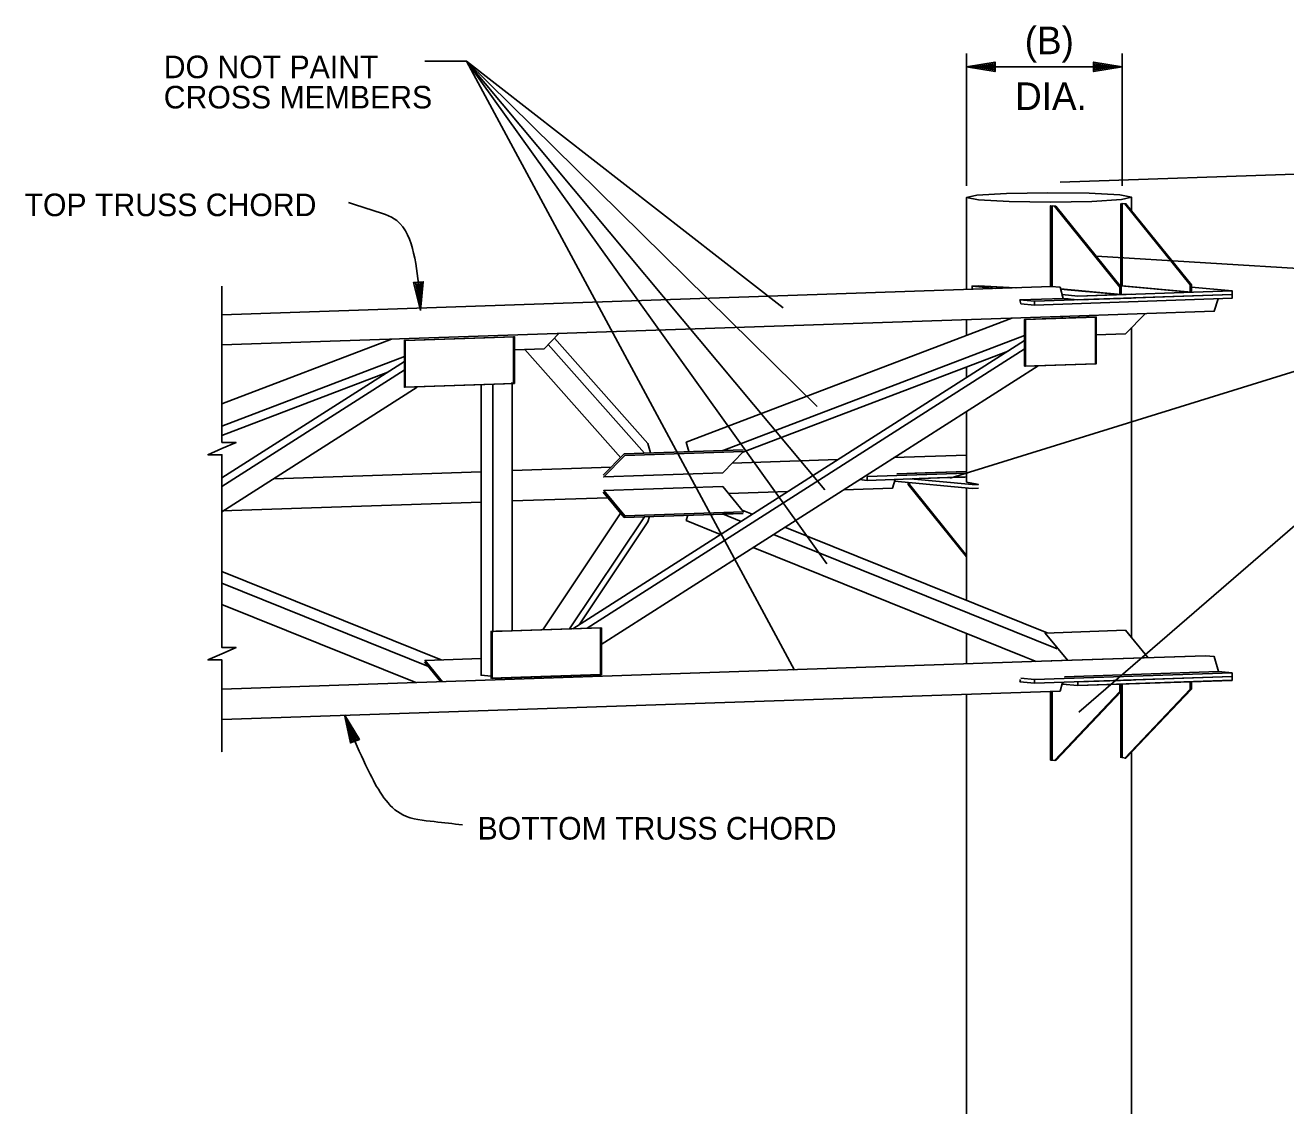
# Model space of a CAD drawing. Extents: x 10268852 to 10269008, y 2142584 to 2142686.
# Drawn here: x 10268877.93 to 10268915.89, y 2142653.26 to 2142685.79 of the extents above; entities that cross this region are included whole.
import ezdxf

# ---------------------------------------------------------------- set-up
doc = ezdxf.new("R2010")
doc.units = 0
doc.layers.add('SignDetail', color=7, linetype='Continuous')
doc.layers.add('TextLabel', color=7, linetype='Continuous')

msp = doc.modelspace()

# ---------------------------------------------------------------- linework, layer by layer
at = {"layer": 'SignDetail'}
msp.add_line((10268914.272, 2142666.07), (10268914.272, 2142666.183), dxfattribs=at)
for points in [[(10268906.277, 2142680.609), (10268906.588, 2142680.679), (10268907.481, 2142680.731), (10268908.717, 2142680.751), (10268909.965, 2142680.734), (10268910.89, 2142680.683), (10268911.246, 2142680.614)], [(10268910.89, 2142680.683), (10268909.965, 2142680.734), (10268908.717, 2142680.751), (10268907.481, 2142680.731), (10268906.588, 2142680.679), (10268906.277, 2142680.609), (10268906.632, 2142680.539), (10268907.558, 2142680.488), (10268908.806, 2142680.471), (10268910.042, 2142680.491), (10268910.935, 2142680.543), (10268911.246, 2142680.614), (10268910.89, 2142680.683)], [(10268906.277, 2142680.609), (10268906.588, 2142680.68)], [(10268906.588, 2142680.68), (10268907.481, 2142680.732)], [(10268907.481, 2142680.732), (10268908.717, 2142680.752)], [(10268908.717, 2142680.752), (10268909.965, 2142680.734)], [(10268909.965, 2142680.734), (10268910.891, 2142680.684), (10268911.246, 2142680.614)], [(10268906.277, 2142677.842), (10268906.277, 2142680.609), (10268906.632, 2142680.539), (10268907.558, 2142680.488), (10268908.806, 2142680.471), (10268910.042, 2142680.491), (10268910.935, 2142680.543), (10268911.246, 2142680.614), (10268911.246, 2142680.208)], [(10268908.806, 2142677.928), (10268908.806, 2142680.359), (10268908.806, 2142677.928)], [(10268908.806, 2142677.928), (10268908.806, 2142680.359), (10268908.922, 2142680.349), (10268910.891, 2142677.908)], [(10268908.806, 2142680.359), (10268908.806, 2142677.928)], [(10268908.806, 2142680.359), (10268908.922, 2142680.349)], [(10268908.842, 2142680.361), (10268908.842, 2142677.927)], [(10268908.842, 2142680.361), (10268908.842, 2142677.927)], [(10268908.856, 2142680.359), (10268908.958, 2142680.35), (10268910.927, 2142677.909), (10268910.927, 2142677.684), (10268909.102, 2142677.855)], [(10268908.856, 2142680.359), (10268908.958, 2142680.35)], [(10268908.856, 2142680.344), (10268908.856, 2142677.925), (10268908.856, 2142680.344)], [(10268910.891, 2142677.683), (10268910.891, 2142677.908), (10268908.922, 2142680.349)], [(10268909.102, 2142677.855), (10268910.927, 2142677.684), (10268910.927, 2142677.909), (10268908.958, 2142680.35)], [(10268913.006, 2142677.754), (10268910.921, 2142677.95), (10268910.921, 2142680.431)], [(10268911.038, 2142680.42), (10268913.006, 2142677.98), (10268913.006, 2142677.754), (10268910.921, 2142677.95), (10268910.921, 2142680.431)], [(10268910.957, 2142677.952), (10268910.957, 2142680.432), (10268911.074, 2142680.422), (10268913.043, 2142677.981)], [(10268913.043, 2142677.981), (10268911.074, 2142680.422), (10268910.957, 2142680.432), (10268910.957, 2142677.952)], [(10268913.006, 2142677.98), (10268911.038, 2142680.42), (10268911.074, 2142680.422)], [(10268883.852, 2142672.464), (10268883.852, 2142672.862), (10268883.426, 2142672.862), (10268883.852, 2142673.047), (10268884.277, 2142673.232), (10268883.852, 2142673.232), (10268883.852, 2142677.939)], [(10268883.85, 2142677.08), (10268908.825, 2142677.928), (10268909.088, 2142677.904), (10268909.185, 2142677.568)], [(10268907.155, 2142677.872), (10268906.439, 2142677.939), (10268906.632, 2142677.946), (10268907.558, 2142677.895), (10268907.761, 2142677.892)], [(10268906.439, 2142677.939), (10268906.632, 2142677.946)], [(10268906.439, 2142677.939), (10268906.632, 2142677.946), (10268907.558, 2142677.895)], [(10268907.155, 2142677.872), (10268906.439, 2142677.939), (10268906.439, 2142677.847)], [(10268907.528, 2142677.897), (10268906.632, 2142677.946), (10268907.528, 2142677.897)], [(10268906.632, 2142677.946), (10268907.558, 2142677.895)], [(10268907.558, 2142677.895), (10268907.764, 2142677.892)], [(10268907.558, 2142677.895), (10268907.761, 2142677.892)], [(10268907.762, 2142677.892), (10268907.558, 2142677.895), (10268907.762, 2142677.892)], [(10268907.878, 2142677.524), (10268908.319, 2142677.482), (10268914.272, 2142677.685), (10268914.272, 2142677.572), (10268908.319, 2142677.369), (10268907.912, 2142677.408)], [(10268907.878, 2142677.524), (10268908.319, 2142677.482), (10268914.272, 2142677.685)], [(10268908.825, 2142677.928), (10268909.088, 2142677.904), (10268909.185, 2142677.568)], [(10268909.185, 2142677.568), (10268909.088, 2142677.904), (10268908.826, 2142677.929)], [(10268910.129, 2142677.759), (10268909.859, 2142677.784), (10268909.102, 2142677.855), (10268909.859, 2142677.784), (10268910.129, 2142677.759)], [(10268910.129, 2142677.759), (10268909.859, 2142677.784), (10268909.102, 2142677.855), (10268909.859, 2142677.784), (10268910.129, 2142677.759)], [(10268909.103, 2142677.85), (10268910.891, 2142677.683), (10268910.891, 2142677.908)], [(10268909.103, 2142677.85), (10268910.891, 2142677.683)], [(10268910.115, 2142677.756), (10268909.853, 2142677.78), (10268909.103, 2142677.85), (10268909.853, 2142677.78), (10268910.115, 2142677.756)], [(10268910.115, 2142677.756), (10268909.853, 2142677.78), (10268909.103, 2142677.85), (10268909.853, 2142677.78), (10268910.115, 2142677.756)], [(10268909.151, 2142677.684), (10268909.626, 2142677.639), (10268914.272, 2142677.798)], [(10268909.151, 2142677.684), (10268909.626, 2142677.639), (10268914.272, 2142677.798)], [(10268909.185, 2142677.568), (10268909.156, 2142677.667)], [(10268909.185, 2142677.568), (10268909.626, 2142677.527), (10268914.272, 2142677.685)], [(10268909.185, 2142677.568), (10268909.626, 2142677.527), (10268914.272, 2142677.685)], [(10268914.272, 2142677.685), (10268909.623, 2142677.527), (10268914.272, 2142677.685)], [(10268909.626, 2142677.639), (10268911.242, 2142677.695)], [(10268909.626, 2142677.527), (10268914.272, 2142677.685), (10268911.889, 2142677.604)], [(10268910.118, 2142677.755), (10268910.891, 2142677.683), (10268910.118, 2142677.755)], [(10268910.118, 2142677.755), (10268910.891, 2142677.683), (10268910.118, 2142677.755)], [(10268910.132, 2142677.759), (10268910.927, 2142677.684), (10268910.132, 2142677.759)], [(10268910.132, 2142677.759), (10268910.927, 2142677.684), (10268910.132, 2142677.759)], [(10268910.896, 2142677.948), (10268910.935, 2142677.95)], [(10268910.896, 2142677.947), (10268910.935, 2142677.95)], [(10268910.896, 2142677.947), (10268910.935, 2142677.95)], [(10268910.935, 2142677.95), (10268910.906, 2142677.948), (10268910.935, 2142677.95)], [(10268910.949, 2142677.951), (10268913.007, 2142677.755), (10268910.949, 2142677.951)], [(10268913.007, 2142677.755), (10268910.949, 2142677.951), (10268913.007, 2142677.755)], [(10268910.957, 2142677.952), (10268913.043, 2142677.756), (10268913.043, 2142677.981)], [(10268913.043, 2142677.981), (10268913.043, 2142677.756), (10268910.957, 2142677.952)], [(10268913.006, 2142677.754), (10268913.006, 2142677.98)], [(10268913.043, 2142677.913), (10268914.272, 2142677.798), (10268913.043, 2142677.913)], [(10268914.272, 2142677.798), (10268913.043, 2142677.913)], [(10268914.272, 2142677.685), (10268914.272, 2142677.798), (10268913.043, 2142677.913)], [(10268907.912, 2142677.408), (10268907.889, 2142677.487), (10268907.879, 2142677.524), (10268909.185, 2142677.568)], [(10268907.879, 2142677.524), (10268909.185, 2142677.568)], [(10268907.912, 2142677.408), (10268908.319, 2142677.369), (10268914.272, 2142677.572)], [(10268907.912, 2142677.408), (10268908.32, 2142677.369)], [(10268908.319, 2142677.369), (10268908.319, 2142677.482)], [(10268908.32, 2142677.37), (10268914.272, 2142677.572)], [(10268909.088, 2142677.026), (10268909.088, 2142677.025), (10268913.733, 2142677.183), (10268913.848, 2142677.557)], [(10268909.185, 2142677.568), (10268909.626, 2142677.527)], [(10268909.332, 2142677.555), (10268909.185, 2142677.568), (10268909.332, 2142677.555)], [(10268909.626, 2142677.527), (10268911.235, 2142677.581)], [(10268909.626, 2142677.527), (10268911.235, 2142677.581)], [(10268883.85, 2142676.167), (10268909.088, 2142677.025), (10268909.088, 2142677.026)], [(10268897.913, 2142672.957), (10268897.831, 2142673.238), (10268907.635, 2142676.976)], [(10268906.277, 2142676.458), (10268906.277, 2142676.929)], [(10268908.052, 2142675.527), (10268908.052, 2142676.936), (10268908.023, 2142676.939), (10268908.023, 2142675.53), (10268910.152, 2142675.602), (10268910.152, 2142677.012), (10268908.023, 2142676.939)], [(10268908.023, 2142675.53), (10268908.052, 2142675.527), (10268910.181, 2142675.6), (10268910.181, 2142677.009), (10268908.052, 2142676.936)], [(10268910.181, 2142675.6), (10268910.181, 2142677.009), (10268908.052, 2142676.936), (10268908.052, 2142675.527), (10268910.181, 2142675.6)], [(10268909.088, 2142677.026), (10268909.088, 2142677.025)], [(10268909.088, 2142677.026), (10268909.088, 2142677.025)], [(10268909.123, 2142676.977), (10268909.173, 2142677.028)], [(10268910.181, 2142676.469), (10268911.06, 2142676.499), (10268911.659, 2142677.113)], [(10268892.667, 2142676.025), (10268893.552, 2142676.055), (10268894, 2142676.514)], [(10268911.246, 2142676.689), (10268911.246, 2142667.35)], [(10268883.85, 2142674.394), (10268888.956, 2142676.341)], [(10268892.635, 2142675.007), (10268889.344, 2142674.895), (10268889.344, 2142676.305), (10268892.635, 2142676.416), (10268892.635, 2142675.007)], [(10268892.664, 2142675.004), (10268892.664, 2142676.414), (10268889.373, 2142676.302), (10268889.373, 2142674.893), (10268892.664, 2142675.004)], [(10268892.664, 2142675.004), (10268889.373, 2142674.893), (10268889.373, 2142676.302), (10268892.664, 2142676.414), (10268892.664, 2142675.004)], [(10268893.673, 2142676.181), (10268896.571, 2142672.911)], [(10268893.861, 2142676.374), (10268896.676, 2142673.199), (10268896.757, 2142672.918)], [(10268894.415, 2142667.625), (10268908.023, 2142676.301)], [(10268898.913, 2142672.982), (10268908.023, 2142676.454)], [(10268883.85, 2142673.726), (10268889.344, 2142675.82)], [(10268892.972, 2142676.034), (10268895.862, 2142672.774)], [(10268894.844, 2142667.642), (10268908.012, 2142676.039)], [(10268899.539, 2142672.941), (10268907.527, 2142675.985)], [(10268908.025, 2142676.004), (10268908.033, 2142676.009)], [(10268908.031, 2142675.949), (10268908.033, 2142676.009)], [(10268883.85, 2142672.164), (10268889.344, 2142675.666)], [(10268889.342, 2142675.41), (10268883.85, 2142671.908)], [(10268883.85, 2142673.445), (10268888.849, 2142675.351)], [(10268908.428, 2142675.543), (10268895.269, 2142667.152)], [(10268906.277, 2142675.509), (10268906.277, 2142675.188)], [(10268908.023, 2142675.53), (10268908.324, 2142675.537)], [(10268891.957, 2142666.195), (10268891.656, 2142666.223), (10268891.656, 2142674.97)], [(10268892.006, 2142667.524), (10268892.006, 2142674.979)], [(10268892.582, 2142675.002), (10268892.582, 2142675.037)], [(10268892.586, 2142675.006), (10268892.586, 2142667.55)], [(10268883.85, 2142671.146), (10268889.732, 2142674.897)], [(10268906.277, 2142674.171), (10268906.277, 2142672.039)], [(10268895.335, 2142672.245), (10268895.965, 2142672.891), (10268899.546, 2142673.012)], [(10268895.335, 2142672.245), (10268895.965, 2142672.891), (10268899.546, 2142673.012)], [(10268899.56, 2142672.962), (10268898.93, 2142672.317), (10268895.35, 2142672.195), (10268895.979, 2142672.84), (10268899.56, 2142672.962)], [(10268898.93, 2142672.317), (10268899.56, 2142672.962), (10268895.979, 2142672.84), (10268895.35, 2142672.195), (10268898.93, 2142672.317)], [(10268898.93, 2142672.317), (10268899.56, 2142672.962), (10268895.979, 2142672.84), (10268895.35, 2142672.195), (10268898.93, 2142672.317)], [(10268898.933, 2142672.989), (10268898.913, 2142672.982), (10268898.933, 2142672.989)], [(10268899.561, 2142672.963), (10268898.93, 2142672.317)], [(10268898.93, 2142672.317), (10268899.561, 2142672.963)], [(10268899.215, 2142672.609), (10268902.402, 2142672.717)], [(10268904.088, 2142672.775), (10268906.277, 2142672.849)], [(10268883.852, 2142663.916), (10268883.852, 2142666.686), (10268883.426, 2142666.686), (10268883.852, 2142666.872), (10268884.277, 2142667.057), (10268883.852, 2142667.057), (10268883.852, 2142672.464)], [(10268885.409, 2142672.14), (10268891.656, 2142672.352)], [(10268892.586, 2142672.384), (10268895.569, 2142672.485)], [(10268895.35, 2142672.195), (10268898.93, 2142672.317)], [(10268895.35, 2142672.195), (10268898.93, 2142672.317)], [(10268903.284, 2142672.092), (10268903.284, 2142672.205), (10268906.277, 2142672.306)], [(10268904.178, 2142672.288), (10268906.277, 2142672.359)], [(10268904.714, 2142672.306), (10268906.277, 2142672.359)], [(10268902.576, 2142671.811), (10268904.046, 2142671.861), (10268904.125, 2142672.12)], [(10268903.051, 2142672.113), (10268903.284, 2142672.092), (10268906.277, 2142672.194)], [(10268904.109, 2142672.068), (10268906.439, 2142671.85), (10268906.632, 2142671.856)], [(10268904.109, 2142672.068), (10268906.439, 2142671.85), (10268906.632, 2142671.856)], [(10268904.109, 2142672.068), (10268906.439, 2142671.85)], [(10268904.177, 2142672.288), (10268904.177, 2142672.289)], [(10268904.516, 2142672.03), (10268904.516, 2142671.967), (10268906.277, 2142669.785)], [(10268904.516, 2142672.03), (10268904.516, 2142671.967), (10268906.277, 2142669.785)], [(10268906.277, 2142669.831), (10268904.553, 2142671.968), (10268904.553, 2142672.027)], [(10268904.553, 2142672.027), (10268904.553, 2142671.968), (10268906.277, 2142669.831)], [(10268904.59, 2142672.136), (10268906.439, 2142671.962), (10268906.632, 2142671.969), (10268906.277, 2142672.039)], [(10268906.439, 2142671.962), (10268904.59, 2142672.136)], [(10268904.671, 2142672.139), (10268904.842, 2142672.145), (10268906.277, 2142672.194)], [(10268904.671, 2142672.139), (10268904.842, 2142672.145), (10268906.277, 2142672.194)], [(10268905.402, 2142672.164), (10268906.222, 2142672.191), (10268906.277, 2142672.194)], [(10268905.402, 2142672.164), (10268906.222, 2142672.191), (10268906.277, 2142672.194)], [(10268906.594, 2142671.973), (10268906.277, 2142672.039)], [(10268906.594, 2142671.973), (10268906.277, 2142672.039)], [(10268906.632, 2142671.969), (10268906.277, 2142672.039)], [(10268906.632, 2142671.969), (10268906.277, 2142672.039)], [(10268906.439, 2142671.962), (10268906.632, 2142671.969)], [(10268892.586, 2142671.471), (10268895.474, 2142671.569)], [(10268895.335, 2142671.738), (10268895.965, 2142670.975)], [(10268895.335, 2142671.738), (10268895.965, 2142670.975), (10268899.546, 2142671.096)], [(10268895.965, 2142670.975), (10268895.979, 2142671.022), (10268895.35, 2142671.786), (10268898.93, 2142671.908), (10268899.56, 2142671.144), (10268895.979, 2142671.022)], [(10268895.35, 2142671.786), (10268898.93, 2142671.908), (10268899.561, 2142671.144)], [(10268895.35, 2142671.786), (10268898.93, 2142671.908), (10268899.561, 2142671.144)], [(10268895.979, 2142671.022), (10268899.56, 2142671.144), (10268898.93, 2142671.908), (10268895.35, 2142671.786), (10268895.979, 2142671.022), (10268895.965, 2142670.975), (10268899.546, 2142671.096)], [(10268899.56, 2142671.144), (10268895.979, 2142671.022), (10268895.35, 2142671.786), (10268898.93, 2142671.908), (10268899.56, 2142671.144)], [(10268899.107, 2142671.693), (10268900.89, 2142671.754)], [(10268906.277, 2142668.472), (10268906.277, 2142671.865)], [(10268906.439, 2142671.85), (10268906.632, 2142671.856)], [(10268883.85, 2142671.174), (10268891.656, 2142671.439)], [(10268899.518, 2142671.195), (10268899.822, 2142671.072)], [(10268893.509, 2142667.594), (10268895.861, 2142671.112)], [(10268894.316, 2142667.621), (10268896.571, 2142670.995)], [(10268894.605, 2142667.746), (10268896.676, 2142670.843), (10268896.724, 2142671)], [(10268897.879, 2142671.04), (10268897.831, 2142670.883), (10268898.869, 2142670.465)], [(10268898.92, 2142671.083), (10268899.546, 2142671.097)], [(10268898.92, 2142671.083), (10268899.484, 2142670.856)], [(10268900.462, 2142670.462), (10268909.001, 2142667.022)], [(10268900.8, 2142670.678), (10268908.699, 2142667.496)], [(10268899.847, 2142670.07), (10268908.015, 2142666.779)], [(10268883.85, 2142669.347), (10268890.451, 2142666.687)], [(10268883.85, 2142668.994), (10268890.122, 2142666.468)], [(10268883.85, 2142668.355), (10268889.689, 2142666.002)], [(10268895.248, 2142666.243), (10268891.957, 2142666.131), (10268891.957, 2142667.541), (10268895.248, 2142667.653)], [(10268895.277, 2142666.24), (10268891.986, 2142666.129), (10268891.986, 2142667.538), (10268895.277, 2142667.65)], [(10268895.277, 2142667.65), (10268895.277, 2142666.24), (10268891.986, 2142666.129), (10268891.986, 2142667.538), (10268895.277, 2142667.65)], [(10268892.095, 2142667.546), (10268892.556, 2142667.561)], [(10268895.248, 2142666.243), (10268895.248, 2142667.653)], [(10268895.277, 2142666.24), (10268895.277, 2142667.65)], [(10268906.277, 2142666.566), (10268906.277, 2142667.479)], [(10268909.32, 2142666.67), (10268908.64, 2142667.494), (10268911.06, 2142667.576), (10268911.74, 2142666.752)], [(10268909.32, 2142666.67), (10268908.64, 2142667.494), (10268911.06, 2142667.576)], [(10268908.641, 2142667.494), (10268911.06, 2142667.576)], [(10268911.06, 2142667.576), (10268911.74, 2142666.752)], [(10268911.06, 2142667.576), (10268911.74, 2142666.752)], [(10268908.964, 2142667.037), (10268909.002, 2142667.022)], [(10268883.85, 2142665.804), (10268908.825, 2142666.653), (10268908.846, 2142666.651)], [(10268890.009, 2142666.556), (10268889.953, 2142666.624)], [(10268890.009, 2142666.556), (10268889.953, 2142666.624)], [(10268890.445, 2142666.028), (10268889.953, 2142666.624)], [(10268889.953, 2142666.624), (10268890.445, 2142666.028)], [(10268890.497, 2142666.03), (10268889.968, 2142666.671), (10268891.656, 2142666.729)], [(10268889.968, 2142666.671), (10268891.656, 2142666.729)], [(10268889.968, 2142666.671), (10268891.656, 2142666.729)], [(10268889.968, 2142666.671), (10268891.656, 2142666.729)], [(10268889.968, 2142666.671), (10268891.656, 2142666.729)], [(10268890.497, 2142666.03), (10268889.968, 2142666.671)], [(10268889.968, 2142666.671), (10268890.497, 2142666.03)], [(10268908.016, 2142666.779), (10268908.367, 2142666.637)], [(10268908.825, 2142666.653), (10268913.471, 2142666.811)], [(10268908.825, 2142666.653), (10268913.471, 2142666.811)], [(10268908.847, 2142666.651), (10268908.825, 2142666.653), (10268913.471, 2142666.811), (10268913.733, 2142666.786), (10268913.864, 2142666.334)], [(10268908.84, 2142666.653), (10268913.471, 2142666.811), (10268913.733, 2142666.786), (10268913.864, 2142666.334)], [(10268890.01, 2142666.556), (10268890.122, 2142666.468), (10268890.062, 2142666.492)], [(10268890.01, 2142666.556), (10268890.122, 2142666.468), (10268890.062, 2142666.492)], [(10268908.319, 2142666.094), (10268914.272, 2142666.296), (10268913.864, 2142666.334)], [(10268908.319, 2142665.981), (10268914.272, 2142666.183), (10268914.272, 2142666.296)], [(10268909.221, 2142666.176), (10268913.864, 2142666.334)], [(10268909.221, 2142666.176), (10268913.864, 2142666.334)], [(10268883.85, 2142664.891), (10268909.088, 2142665.749), (10268909.167, 2142666.01)], [(10268894.039, 2142666.198), (10268894.078, 2142666.152)], [(10268894.078, 2142666.151), (10268894.039, 2142666.198)], [(10268894.039, 2142666.198), (10268894.078, 2142666.152)], [(10268894.039, 2142666.198), (10268894.078, 2142666.151)], [(10268894.078, 2142666.151), (10268894.039, 2142666.198)], [(10268907.912, 2142666.132), (10268908.319, 2142666.094), (10268908.319, 2142665.981), (10268907.878, 2142666.022)], [(10268907.902, 2142666.098), (10268907.879, 2142666.022)], [(10268908.806, 2142663.67), (10268908.922, 2142663.66), (10268910.891, 2142665.73), (10268910.891, 2142665.955)], [(10268908.806, 2142663.67), (10268908.922, 2142663.66), (10268910.891, 2142665.73), (10268910.891, 2142665.955)], [(10268908.856, 2142663.67), (10268908.958, 2142663.661), (10268910.927, 2142665.731), (10268910.927, 2142665.957)], [(10268910.927, 2142665.957), (10268910.927, 2142665.731), (10268908.958, 2142663.661), (10268908.856, 2142663.67)], [(10268909.151, 2142665.957), (10268909.626, 2142665.912)], [(10268909.626, 2142665.912), (10268909.151, 2142665.957)], [(10268909.151, 2142665.957), (10268909.626, 2142665.912)], [(10268909.285, 2142665.947), (10268909.152, 2142665.961)], [(10268909.152, 2142665.961), (10268909.285, 2142665.947)], [(10268909.626, 2142666.025), (10268914.272, 2142666.186)], [(10268914.272, 2142666.183), (10268909.626, 2142666.025), (10268909.626, 2142665.912), (10268914.272, 2142666.07)], [(10268909.626, 2142666.025), (10268911.235, 2142666.08)], [(10268909.626, 2142665.912), (10268914.272, 2142666.071)], [(10268909.626, 2142665.912), (10268914.272, 2142666.07)], [(10268910.935, 2142663.756), (10268910.935, 2142665.957), (10268910.935, 2142663.756), (10268910.935, 2142665.957), (10268910.935, 2142663.756)], [(10268910.935, 2142665.957), (10268910.935, 2142665.268), (10268910.935, 2142663.743)], [(10268910.957, 2142665.957), (10268910.957, 2142663.744), (10268911.074, 2142663.732), (10268913.043, 2142665.803), (10268913.043, 2142666.028)], [(10268911.074, 2142663.732), (10268910.957, 2142663.744), (10268910.957, 2142665.957)], [(10268913.006, 2142666.027), (10268913.006, 2142665.802), (10268911.038, 2142663.731), (10268911.074, 2142663.732), (10268913.043, 2142665.803), (10268913.043, 2142666.028)], [(10268911.038, 2142663.731), (10268913.006, 2142665.802), (10268913.006, 2142666.027)], [(10268911.888, 2142666.102), (10268914.272, 2142666.183)], [(10268906.277, 2142665.654), (10268906.277, 2142631.914)], [(10268908.806, 2142665.74), (10268908.806, 2142663.67)], [(10268908.806, 2142663.671), (10268908.806, 2142665.74), (10268908.806, 2142663.671), (10268908.806, 2142665.74), (10268908.806, 2142663.671)], [(10268908.806, 2142663.67), (10268908.806, 2142665.74)], [(10268908.806, 2142663.67), (10268908.806, 2142665.74)], [(10268908.842, 2142665.741), (10268908.842, 2142663.671)], [(10268908.842, 2142665.741), (10268908.842, 2142663.671)], [(10268908.856, 2142665.741), (10268908.856, 2142663.686), (10268908.856, 2142665.741)], [(10268910.921, 2142663.742), (10268910.921, 2142665.725)], [(10268910.921, 2142665.725), (10268910.921, 2142663.742)], [(10268911.246, 2142663.913), (10268911.246, 2142631.798)]]:
    msp.add_lwpolyline(points, dxfattribs=at)
msp.add_arc((10268883.845, 2142663.906), 0.00593, 0, 88.0534, dxfattribs=at)
at = {"layer": 'TextLabel'}
for p, q in [((10268906.277, 2142680.957), (10268906.277, 2142684.948)), ((10268910.957, 2142680.957), (10268910.957, 2142684.948)), ((10268891.217, 2142684.71), (10268889.961, 2142684.71)), ((10268900.751, 2142677.287), (10268891.217, 2142684.71)), ((10268891.217, 2142684.71), (10268901.778, 2142674.317)), ((10268902.007, 2142671.804), (10268891.217, 2142684.71)), ((10268901.093, 2142666.378), (10268891.217, 2142684.71)), ((10268902.064, 2142669.577), (10268891.217, 2142684.71)), ((10268906.277, 2142684.543), (10268910.957, 2142684.543)), ((10268924.858, 2142681.606), (10268909.088, 2142681.07)), ((10268910.186, 2142678.846), (10268924.506, 2142677.966)), ((10268905.784, 2142672.153), (10268924.506, 2142677.966)), ((10268909.658, 2142665.108), (10268924.506, 2142677.966))]:
    msp.add_line(p, q, dxfattribs=at)
for points in [[(10268906.277, 2142684.543), (10268907.135, 2142684.687), (10268907.135, 2142684.399)], [(10268906.531, 2142684.543), (10268907.107, 2142684.633), (10268907.107, 2142684.454)], [(10268906.764, 2142684.543), (10268907.06, 2142684.591), (10268907.06, 2142684.495)], [(10268910.957, 2142684.543), (10268910.1, 2142684.399), (10268910.1, 2142684.687)], [(10268910.704, 2142684.543), (10268910.127, 2142684.454), (10268910.127, 2142684.632)], [(10268910.47, 2142684.543), (10268910.175, 2142684.495), (10268910.175, 2142684.591)], [(10268889.826, 2142677.205), (10268889.623, 2142678.051), (10268889.911, 2142678.071)], [(10268889.809, 2142677.458), (10268889.68, 2142678.027), (10268889.858, 2142678.039)], [(10268889.793, 2142677.691), (10268889.724, 2142677.982), (10268889.821, 2142677.989)], [(10268887.538, 2142665.035), (10268887.989, 2142664.291), (10268887.721, 2142664.185)], [(10268887.632, 2142664.799), (10268887.928, 2142664.297), (10268887.762, 2142664.231)], [(10268887.718, 2142664.582), (10268887.872, 2142664.326), (10268887.783, 2142664.29)]]:
    msp.add_lwpolyline(points, close=True, dxfattribs=at)
for points in [[(10268887.66, 2142680.456), (10268888.405, 2142680.218), (10268889.114, 2142679.914), (10268889.624, 2142678.932), (10268889.791, 2142677.712), (10268889.826, 2142677.205)], [(10268891.093, 2142661.717), (10268890.246, 2142661.816), (10268889.299, 2142662.021), (10268888.317, 2142663.241), (10268887.808, 2142664.358), (10268887.538, 2142665.035)]]:
    msp.add_spline(points, degree=3, dxfattribs=at)

# ---------------------------------------------------------------- texts
for s, height, p in [('(B)', 0.83, (10268908.026, 2142684.921)), ('DO NOT PAINT ', 0.68, (10268882.098, 2142684.2)), ('DIA.', 0.83, (10268907.737, 2142683.243)), ('CROSS MEMBERS', 0.68, (10268882.098, 2142683.289)), ('TOP TRUSS CHORD', 0.68, (10268877.906, 2142680.046)), ('BOTTOM TRUSS CHORD', 0.68, (10268891.55, 2142661.276))]:
    msp.add_text(s, height=height, dxfattribs=at).set_placement(p)

doc.saveas('drawing.dxf')
